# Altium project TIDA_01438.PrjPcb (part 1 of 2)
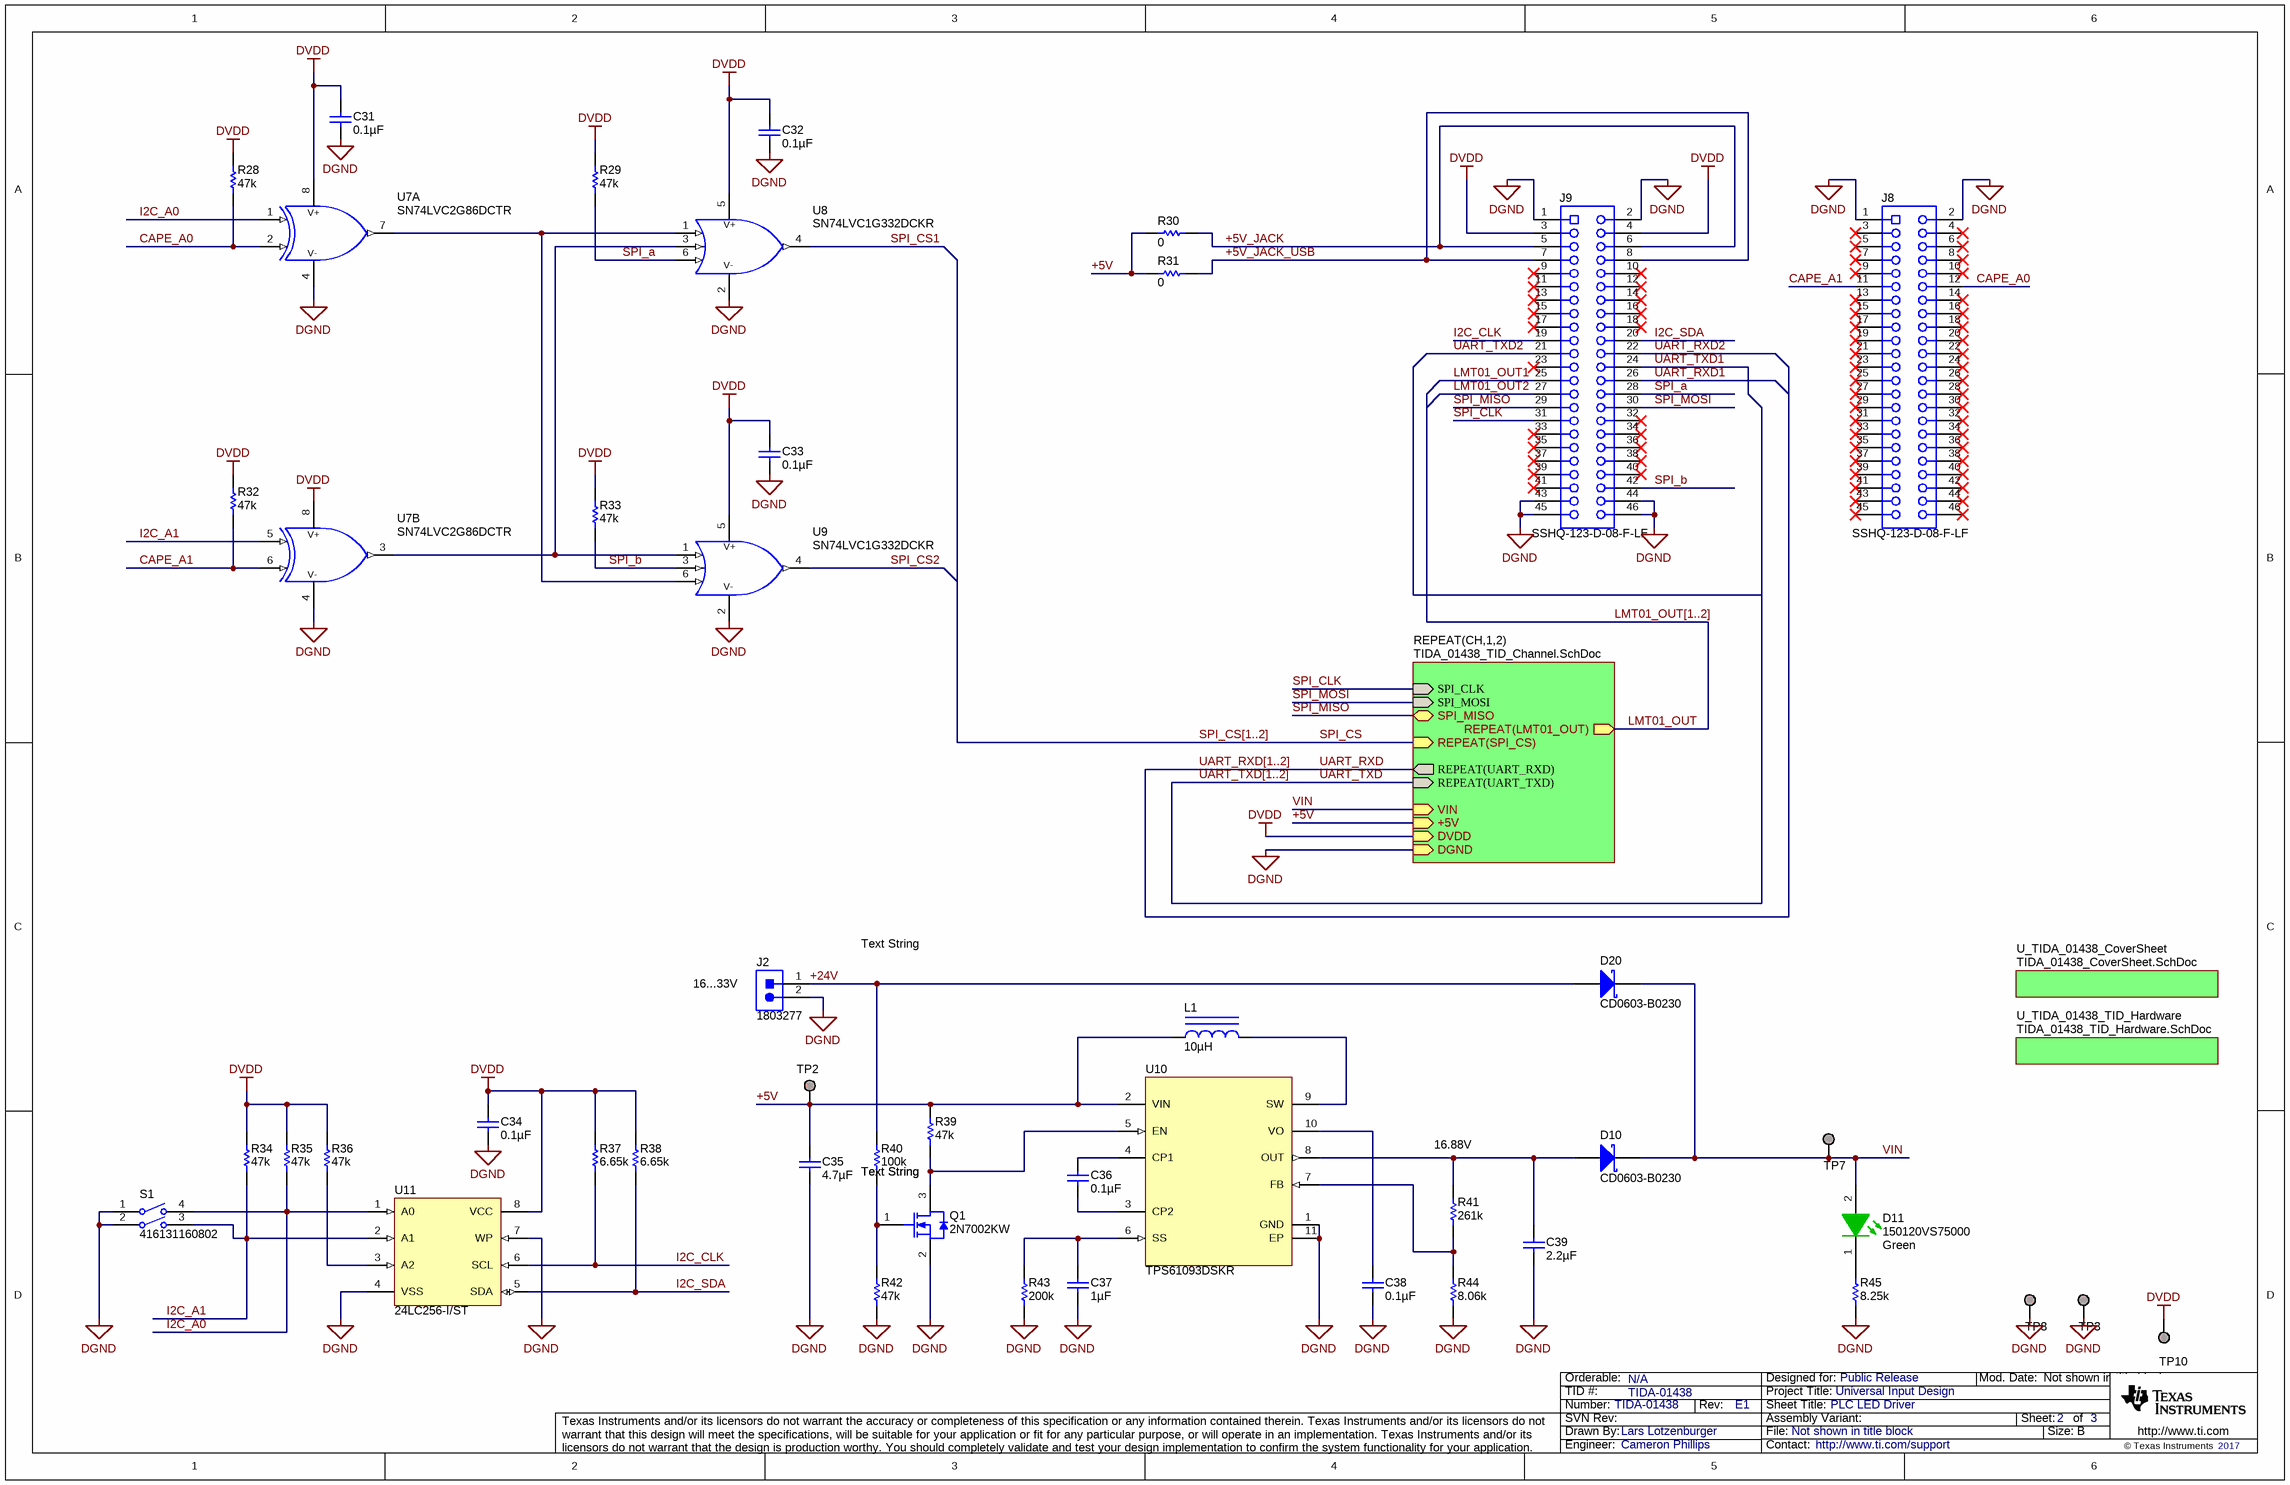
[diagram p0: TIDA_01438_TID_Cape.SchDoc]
TID: TIDA-01438; TechSupport: http://www.ti.com/support; SCH_Rev: E1; PRJ_Title: Universal Input Design; PRJ_Number: TIDA-01438; PRJ_Engineer: Cameron Phillips; PRJ_Customer: Public Release; PCB_Rev: E1; PCB_Layout: Cameron Phillips; EVM_Orderable: N/A; CopyrightYear: 2017
8 sheets, 365 parts. Net scope: strictly hierarchical (ports join the sheet entries above them; power ports are local).
Board file: TIDA_01438_TID.PcbDoc
Sheets:
  TIDA_01438_TID_Cape.SchDoc
    CH1 = TIDA_01438_TID_Channel.SchDoc
      AFE = TIDA_01438_TID_AFE.SchDoc
      PWR = TIDA_01438_TID_Power.SchDoc
      ADC = TIDA_01438_TID_ADS1262.SchDoc
      HART = TIDA_01438_TID_HART.SchDoc
    CH2 = TIDA_01438_TID_Channel.SchDoc
      AFE = TIDA_01438_TID_AFE.SchDoc
      PWR = TIDA_01438_TID_Power.SchDoc
      ADC = TIDA_01438_TID_ADS1262.SchDoc
      HART = TIDA_01438_TID_HART.SchDoc
    U_TIDA_01438_CoverSheet = TIDA_01438_CoverSheet.SchDoc
    U_TIDA_01438_TID_Hardware = TIDA_01438_TID_Hardware.SchDoc

## Sheet TIDA_01438_TID_Cape.SchDoc: PLC LED Driver
size 431 x 279 mm; Date: Not shown in title block; ApprovedBy: Not shown in title block; CheckedBy: Not shown in title block; Author: Not shown in title block; CompanyName: Not shown in title block; DrawnBy: Lars Lotzenburger; Engineer: Not shown in title block; Organization: Not shown in title block; Address1: Not shown in title block; Address2: Not shown in title block; Address3: Not shown in title block; Address4: Not shown in title block; DocumentNumber: 2; Revision: Use project parameter SCH_Rev; SheetNumber: 2; SheetTotal: 3; PageSetup: Record=PageOptions¦CenterHorizontal=True¦CenterVertical=True¦PrintScale=0.62¦XCorrection=1.00¦YCorrection=1.00¦PrintKind=0¦BorderSize=5000000¦LeftOffset=0¦BottomOffset=0¦Orientation=2¦PaperLength=1000¦PaperWidth=1000¦Scale=100¦PaperSource=15¦PrintQuality=600¦MediaType=1¦DitherType=10¦PrintScaleMode=1¦PaperKind=Letter

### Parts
C31  ValueDisplayed: 0.1µF  [0402]  (hidden comment: C1005X7R1H104K)
C32  ValueDisplayed: 0.1µF  [0402]  (hidden comment: C1005X7R1H104K)
C33  ValueDisplayed: 0.1µF  [0402]  (hidden comment: C1005X7R1H104K)
C34  ValueDisplayed: 0.1µF  [0402]  (hidden comment: C1005X7R1H104K)
C35  ValueDisplayed: 4.7µF  [1206_190]  (hidden comment: C3216X7R1H475M160AC)
C36  ValueDisplayed: 0.1µF  [0402]  (hidden comment: C1005X7R1H104K)
C37  ValueDisplayed: 1µF  [0603]  (hidden comment: C1608X7R1C105K)
C38  ValueDisplayed: 0.1µF  [0402]  (hidden comment: C1005X7R1H104K)
C39  ValueDisplayed: 2.2µF  [1206]  (hidden comment: UMK316B7225KL-T)
D10  CD0603-B0230  [Diode_0603]
D11  150120VS75000  value Green  [WL_SMCW_GREEN_1206]
D20  CD0603-B0230  [Diode_0603]
J2  1803277  [PhoenixContact_1803277]
J8  SSHQ-123-D-08-F-LF  [Major_BBB_SSHQ-123-D-08]
J9  SSHQ-123-D-08-F-LF  [Major_BBB_SSHQ-123-D-08]
L1  ValueDisplayed: 10µH  [WE-LQS_4018]  (hidden comment: 74404042100)
Q1  2N7002KW  [SOT-323]
R28  ValueDisplayed: 47k  [0402]  (hidden comment: CRCW040247K0JNED)
R29  ValueDisplayed: 47k  [0402]  (hidden comment: CRCW040247K0JNED)
R30  ValueDisplayed: 0  [0603]  (hidden comment: ERJ-3GEY0R00V)
R31  ValueDisplayed: 0  [0603]  (hidden comment: ERJ-3GEY0R00V)
R32  ValueDisplayed: 47k  [0402]  (hidden comment: CRCW040247K0JNED)
R33  ValueDisplayed: 47k  [0402]  (hidden comment: CRCW040247K0JNED)
R34  ValueDisplayed: 47k  [0402]  (hidden comment: CRCW040247K0JNED)
R35  ValueDisplayed: 47k  [0402]  (hidden comment: CRCW040247K0JNED)
R36  ValueDisplayed: 47k  [0402]  (hidden comment: CRCW040247K0JNED)
R37  ValueDisplayed: 6.65k  [0402]  (hidden comment: CRCW04026K65FKED)
R38  ValueDisplayed: 6.65k  [0402]  (hidden comment: CRCW04026K65FKED)
R39  ValueDisplayed: 47k  [0402]  (hidden comment: CRCW040247K0JNED)
R40  ValueDisplayed: 100k  [0402]  (hidden comment: CRCW0402100KFKED)
R41  ValueDisplayed: 261k  [0402]  (hidden comment: CRCW0402261KFKED)
R42  ValueDisplayed: 47k  [0402]  (hidden comment: CRCW040247K0JNED)
R43  ValueDisplayed: 200k  [0402]  (hidden comment: CRCW0402200KFKED)
R44  ValueDisplayed: 8.06k  [0402]  (hidden comment: CRCW04028K06FKED)
R45  ValueDisplayed: 8.25k  [0402]  (hidden comment: CRCW04028K25FKED)
S1  416131160802  [SW_416131160802]
TP2  TESTPOINT  [TESTPOINT]  (value not drawn)  (no BOM)
TP3  TESTPOINT  [TESTPOINT]  (value not drawn)  (no BOM)
TP7  TESTPOINT  [TESTPOINT]  (value not drawn)  (no BOM)
TP8  TESTPOINT  [TESTPOINT]  (value not drawn)  (no BOM)
TP10  TESTPOINT  [TESTPOINT]  (value not drawn)  (no BOM)
U7  SN74LVC2G86DCTR  [DCT0008A_N]  (parts A,B of 2)
U8  SN74LVC1G332DCKR  [DCK0006A_N]
U9  SN74LVC1G332DCKR  [DCK0006A_N]
U10  TPS61093DSKR  [DSK0010A]
U11  24LC256-I/ST  [TSSOP-8]

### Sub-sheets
REPEAT(CH,1,2) = TIDA_01438_TID_Channel.SchDoc: SPI_CLK (in), SPI_MOSI (in), REPEAT(UART_RXD) (out), REPEAT(UART_TXD) (in), REPEAT(SPI_CS) (in), SPI_MISO, VIN (in), +5V (in), DGND (in), DVDD (in), REPEAT(LMT01_OUT) (out)
U_TIDA_01438_CoverSheet = TIDA_01438_CoverSheet.SchDoc: no entries
U_TIDA_01438_TID_Hardware = TIDA_01438_TID_Hardware.SchDoc: no entries

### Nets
DGND: C31.2 C32.2 C33.2 C34.2 C35.2 C37.2 C38.2 C39.2 J2.2 J8.1 J8.2 J9.1 J9.2 J9.43 J9.44 J9.45 J9.46 Q1.2(S) R42.1 R43.2 R44.1 R45.1 S1.1 S1.2 TP3.1 TP8.1 U7.4(GND) U8.2(GND) U9.2(GND) U10.1(GND) U10.11(EP) U11.4(VSS) U11.7(WP) ; sheet REPEAT(CH,1,2)/DGND
DVDD: C31.1 C32.1 C33.1 C34.1 J9.3 J9.4 R28.1 R29.1 R32.1 R33.1 R34.1 R35.1 R36.1 R37.1 R38.1 TP10.1 U7.8(VCC) U8.5(VCC) U9.5(VCC) U11.8(VCC) ; sheet REPEAT(CH,1,2)/DVDD
+5V: C35.1 L1.1 R30.1 R31.1 R39.2 TP2.1 U10.2(VIN) ; sheet REPEAT(CH,1,2)/+5V
+5V_JACK: J9.5 J9.6 R30.2
+5V_JACK_USB: J9.7 J9.8 R31.2
+24V: D20.2(A) J2.1 R40.2
CAPE_A0: J8.12 R28.2 U7.2(1B)
CAPE_A1: J8.11 R32.2 U7.6(2B)
I2C_A0: R35.2 S1.4 U7.1(1A) U11.1(A0)
I2C_A1: R34.2 S1.3 U7.5(2A) U11.2(A1)
I2C_CLK: J9.19 R37.2 U11.6(SCL)
I2C_SDA: J9.20 R38.2 U11.5(SDA)
LMT01_OUT1: J9.25
LMT01_OUT2: J9.27
SPI_a: J9.28 R29.2 U8.6(C)
SPI_b: J9.42 R33.2 U9.3(B)
SPI_CLK: J9.31 ; sheet REPEAT(CH,1,2)/SPI_CLK
SPI_CS1: U8.4(Y)
SPI_CS2: U9.4(Y)
SPI_MISO: J9.29 ; sheet REPEAT(CH,1,2)/SPI_MISO
SPI_MOSI: J9.30 ; sheet REPEAT(CH,1,2)/SPI_MOSI
UART_RXD1: J9.26
UART_RXD2: J9.22
UART_TXD1: J9.24
UART_TXD2: J9.21
VIN: D10.1(K) D11.2(A) D20.1(K) TP7.1 ; sheet REPEAT(CH,1,2)/VIN
NetC36_1: C36.1 U10.4(CP1)
NetC36_2: C36.2 U10.3(CP2)
NetC37_1: C37.1 R43.1 U10.6(SS)
NetC38_1: C38.1 U10.10(VO)
NetC39_1: C39.1 D10.2(A) R41.2 U10.8(OUT)
NetD11_1: D11.1(K) R45.2
NetL1_2: L1.2 U10.9(SW)
NetQ1_1: Q1.1(G) R40.1 R42.2
NetQ1_3: Q1.3(D) R39.1 U10.5(EN)
NetR36_2: R36.2 U11.3(A2)
NetR41_1: R41.1 R44.2 U10.7(FB)
NetU7_3: U7.3(2Y) U8.3(B) U9.1(A)
NetU7_7: U7.7(1Y) U8.1(A) U9.6(C)

Not connected (* = marked no-connect by the designer): J8 3* 4* 5* 6* 7* 8* 9* 10* 13* 14* 15* 16* 17* 18* 19* 20* 21* 22* 23* 24* 25* 26* 27* 28* 29* 30* 31* 32* 33* 34* 35* 36* 37* 38* 39* 40* 41* 42* 43* 44* 45* 46*; J9 9* 10* 11* 12* 13* 14* 15* 16* 17* 18* 23* 32* 33* 34* 35* 36* 37* 38* 39* 40* 41*

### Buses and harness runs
bus LMT01_OUT[1..2]
bus SPI_CS[1..2]
bus UART_RXD[1..2]
bus UART_TXD[1..2]

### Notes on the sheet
- Text String
- (near J2) 16...33V
- (near R40) Text String
- (near R41) 16.88V

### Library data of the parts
C31-C34 C36 C38 = C1005X7R1H104K: CAP, CERM, 0.1 µF, 50 V, +/- 10%, X7R, 0402; Manufacturer: TDK; Polarized: N; CompType: Capacitor; Value: 0.1uF; U/M: EA; Cap_F: 0.0000001; Tolerance_%: 10; Value1: Unknown; VDC_V: 50; Value2: 50V; TaMin_C: -55; TaMax_C: 125; AEC Category: Q200
C35 = C3216X7R1H475M160AC: CAP, CERM, 4.7 µF, 50 V, +/- 20%, X7R, 1206_190; Manufacturer: TDK; Polarized: N; CompType: Capacitor; Value: 4.7uF; U/M: EA; Cap_F: 0.0000047; Tolerance_%: 20; Value1: Unknown; VDC_V: 50; Value2: 50V; TaMin_C: -55; TaMax_C: 125; Cap_Case: 1206; AEC Category: Q200
C37 = C1608X7R1C105K: CAP, CERM, 1 µF, 16 V, +/- 10%, X7R, 0603; Manufacturer: TDK; Polarized: N; CompType: Capacitor; Value: 1uF; U/M: EA; Cap_F: 0.000001; Tolerance_%: 10; ESR_ohm: 0.0057; Value1: 0.0057 ohm; VDC_V: 16; Value2: 16V; TaMin_C: -55; TaMax_C: 125
C39 = UMK316B7225KL-T: CAP, CERM, 2.2 µF, 50 V, +/- 10%, X7R, 1206; Manufacturer: Taiyo Yuden; Polarized: N; CompType: Capacitor; Value: 2.2uF; U/M: EA; Cap_F: 0.0000022; Tolerance_%: 10; Value1: Unknown; VDC_V: 50; Value2: 50V; TaMin_C: -55; TaMax_C: 125; AEC Category: Q200
D10 D20 = CD0603-B0230: Diode, Schottky, 35 V, 0.2 A, 0603 Diode; Manufacturer: Bourns; U/M: EA; Vf_V: 0.5; Value: 35V; Value1: 0.2A; Value2: 0.5V; Io_A: 0.2; Vr_V: 35; TJmax_C: 125; AEC Category: Q101
D11 = 150120VS75000: LED, Green, SMD; Manufacturer: Wurth Elektronik; SymbolCreator: Altium; Type: AlInGaP; Vf_V: 2; Value2: 2V; Io_A: 0.02; Vr_V: 5; Ir_A: 1e-005; Tjmax_C: 85; Power_TotalModule: 0.072; Value1: 0.072W; Angle: 140; U/M: EA
J2 = 1803277: Terminal Block, 2x1, 3.81mm, R/A, TH; Manufacturer: Phoenix Contact; SymbolCreator: a0412235; U/M: EA
J8 J9 = SSHQ-123-D-08-F-LF: Female Connector, 2.54mm, 23x2, TH; Manufacturer: Major League Electronics; SymbolCreator: Altium; CompType: Receptacle; U/M: EA
L1 = 74404042100: Inductor, Wirewound, Ferrite, 10 µH, 1.2 A, 0.15 ohm, SMD; Manufacturer: Wurth Elektronik; Value: 10uH; Ind_H: 10.0E-6; Imax_A: 1.2; Irms: 1.2A @ 40C rise; Isat: 1.5A @ 30% inductance drop; DCR_ohm: 0.15; Value2: 1.2A; AEC Category: Q200; AEC Qualified: N
Q1 = 2N7002KW: MOSFET, N-CH, 60 V, 0.31 A, SOT-323; Manufacturer: Fairchild Semiconductor; Alternate Manufacturer: None; U/M: EA; ChType: N; Value: 60V; VdsMax_V: 60; Value1: 1.6 ohm; Rdson45_ohm: 1.6; Value2: ? nC; Vgs_V: 2.1; IdsMax_A: 0.31; AEC Category: Q101
R28 R29 R32 R33 = CRCW040247K0JNED: RES, 47 k, 5%, 0.063 W, 0402; Manufacturer: Vishay-Dale; CompType: Resistor; Value: 47k; Res_ohm: 47000; Value_Code: 47k0; Tolerance_%: 5; Power_W: 0.063; Value2: 0.063W; VDC_V: 50; TempCo: 200 ppm/C; EIA_Code: E24; U/M: EA
R30 R31 = ERJ-3GEY0R00V: RES, 0, 5%, 0.1 W, 0603; Manufacturer: Panasonic; CompType: Resistor; Value: 0; Value_Code: 0000; Tolerance_%: 5; Power_W: 0.1; Value2: 0.1W; VDC_V: 50; TempCo: 600 ppm/C; EIA_Code: E24; U/M: EA; AEC Category: Q200
R34-R36 R39 R42 = CRCW040247K0JNED: RES, 47 k, 5%, 0.063 W, 0402; Manufacturer: Vishay-Dale; CompType: Resistor; Value: 47k; Res_ohm: 47000; Value_Code: 47k0; Tolerance_%: 5; Power_W: 0.063; Value2: 0.063W; VDC_V: 50; TempCo: 200 ppm/C; EIA_Code: E24; U/M: EA; AEC Category: Q200
R37 R38 = CRCW04026K65FKED: RES, 6.65 k, 1%, 0.063 W, 0402; Manufacturer: Vishay-Dale; CompType: Resistor; Value: 6.65k; Res_ohm: 6650; Value_Code: 6k65; Tolerance_%: 1; Power_W: 0.063; Value2: 0.063W; VDC_V: 50; TempCo: 100 ppm/C; EIA_Code: E96; U/M: EA; AEC Category: Q200
R40 = CRCW0402100KFKED: RES, 100 k, 1%, 0.063 W, 0402; Manufacturer: Vishay-Dale; CompType: Resistor; Value: 100k; Res_ohm: 100000; Tolerance_%: 1; Power_W: 0.063; Value2: 0.063W; VDC_V: 50; TempCo: 100 ppm/C; EIA_Code: E96; U/M: EA; AEC Category: Q200
R41 = CRCW0402261KFKED: RES, 261 k, 1%, 0.063 W, 0402; Manufacturer: Vishay-Dale; CompType: Resistor; Value: 261k; Res_ohm: 261000; Tolerance_%: 1; Power_W: 0.063; Value2: 0.063W; VDC_V: 50; TempCo: 100 ppm/C; EIA_Code: E96; U/M: EA; AEC Category: Q200
R43 = CRCW0402200KFKED: RES, 200 k, 1%, 0.063 W, 0402; Manufacturer: Vishay-Dale; CompType: Resistor; Value: 200k; Res_ohm: 200000; Tolerance_%: 1; Power_W: 0.063; Value2: 0.063W; VDC_V: 50; TempCo: 100 ppm/C; EIA_Code: E96; U/M: EA; AEC Category: Q200
R44 = CRCW04028K06FKED: RES, 8.06 k, 1%, 0.063 W, 0402; Manufacturer: Vishay-Dale; CompType: Resistor; Value: 8.06k; Res_ohm: 8060; Value_Code: 8k06; Tolerance_%: 1; Power_W: 0.063; Value2: 0.063W; VDC_V: 50; TempCo: 100 ppm/C; EIA_Code: E96; U/M: EA; AEC Category: Q200
R45 = CRCW04028K25FKED: RES, 8.25 k, 1%, 0.063 W, 0402; Manufacturer: Vishay-Dale; CompType: Resistor; Value: 8.25k; Res_ohm: 8250; Value_Code: 8k25; Tolerance_%: 1; Power_W: 0.063; Value2: 0.063W; VDC_V: 50; TempCo: 100 ppm/C; EIA_Code: E96; U/M: EA; AEC Category: Q200
S1 = 416131160802: Switch, SPST, Off-On, 2 Pos, SMD; Manufacturer: Wurth Elektronik; SymbolCreator: Altium; VDC_V: 24; PositionCount: 2; CurrentRating_mA: 25
TP2 TP3 TP7 TP8 TP10 = TESTPOINT: TEST POINT.  No entry in BOM.
U7 = SN74LVC2G86DCTR: Dual 2-Input Exclusive-OR Gate, DCT0008A; Manufacturer: Texas Instruments; SymbolCreator: a0411947; CompType: IC; U/M: EA
U8 U9 = SN74LVC1G332DCKR: Single 3-Input Positive-OR Gate, DCK0006A; Manufacturer: Texas Instruments; SymbolCreator: Altium; CompType: IC; U/M: EA
U10 = TPS61093DSKR: LOW INPUT BOOST CONVERTER WITH INTEGRATED POWER DIODE AND INPUT/OUTPUT ISOLATION, DSK0010A; Manufacturer: Texas Instruments; SymbolCreator: Altium; CompType: IC; U/M: EA
U11 = 24LC256-I/ST: 256K I2C CMOS Serial EEPROM, TSSOP-8; Manufacturer: Microchip; SymbolCreator: a0411947

## Sheet TIDA_01438_TID_Channel.SchDoc
size 431 x 279 mm; Date: Not shown in title block; ApprovedBy: Not shown in title block; CheckedBy: Not shown in title block; Author: Not shown in title block; CompanyName: Not shown in title block; Engineer: Not shown in title block; Organization: Not shown in title block; Address1: Not shown in title block; Address2: Not shown in title block; Address3: Not shown in title block; Address4: Not shown in title block; DocumentNumber: 1; Revision: Use project parameter SCH_Rev; SheetNumber: 2; SheetTotal: 3; PageSetup: Record=PageOptions¦CenterHorizontal=True¦CenterVertical=True¦PrintScale=1.00¦XCorrection=1.00¦YCorrection=1.00¦PrintKind=0¦BorderSize=5000000¦LeftOffset=0¦BottomOffset=0¦Orientation=2¦PaperLength=1000¦PaperWidth=1000¦Scale=100¦PaperSource=15¦PrintQuality=600¦MediaType=1¦DitherType=10¦PaperKind=Letter¦PrintScaleMode=1
Used 2 times, as channels CH1, CH2. Parts and nets are listed once, with the designators drawn on the sheet.
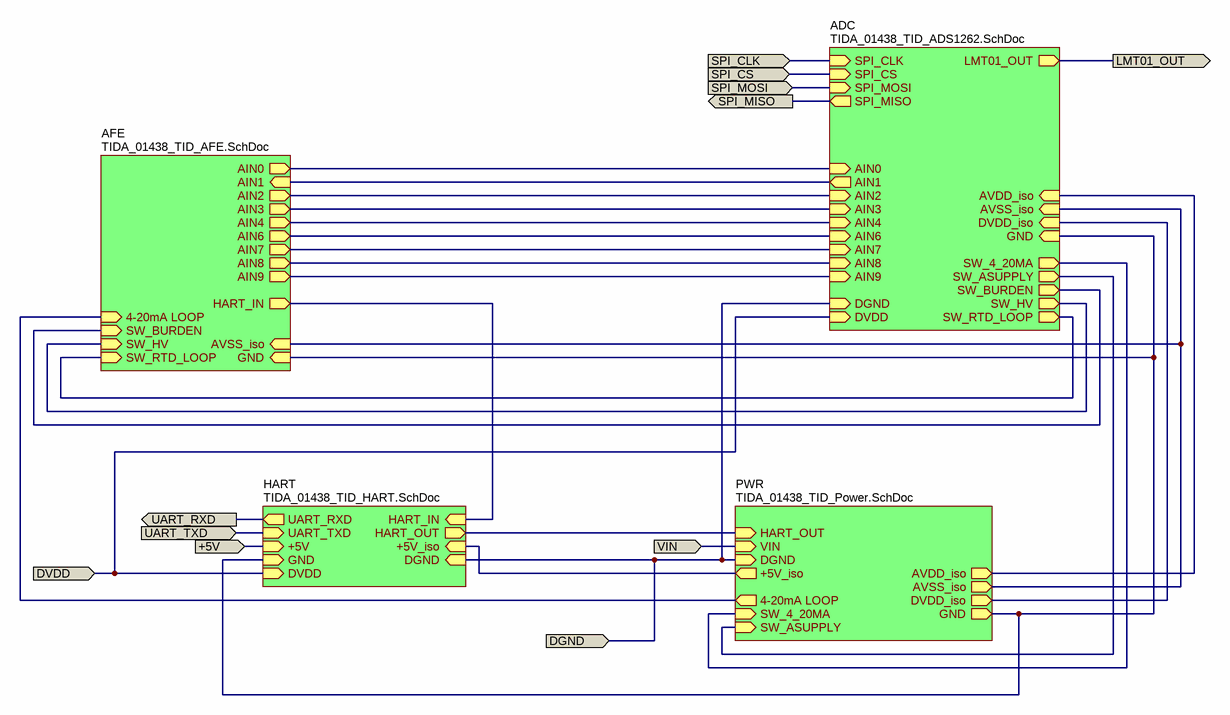
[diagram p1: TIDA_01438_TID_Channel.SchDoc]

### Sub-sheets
ADC = TIDA_01438_TID_ADS1262.SchDoc: SPI_CLK (in), SPI_MOSI (in), SPI_CS (in), AIN8 (in), AIN9 (in), AIN0 (in), AIN7 (in), AIN6 (in), AIN4 (in), SW_RTD_LOOP (out), SW_HV (out), SW_BURDEN (out), SW_4_20MA (out), SW_ASUPPLY (out), AIN1 (out), AIN2 (in), AIN3 (in), SPI_MISO (out), GND (in), AVSS_iso (in), DVDD_iso (in), AVDD_iso (in), DGND (in), DVDD (in), LMT01_OUT (out)
AFE = TIDA_01438_TID_AFE.SchDoc: AIN0 (out), AIN8 (out), AIN4 (out), AIN6 (out), AIN7 (out), AIN9 (out), HART_IN (out), 4-20mA LOOP (in), SW_RTD_LOOP (in), SW_HV (in), SW_BURDEN (in), AIN1 (in), AIN2 (out), AIN3 (out), GND (in), AVSS_iso (in)
HART = TIDA_01438_TID_HART.SchDoc: HART_IN (in), UART_RXD (out), UART_TXD (in), HART_OUT (out), GND (in), +5V (in), DGND (in), DVDD (in), +5V_iso (in)
PWR = TIDA_01438_TID_Power.SchDoc: HART_OUT (in), 4-20mA LOOP (out), SW_4_20MA (in), VIN (in), GND (out), AVSS_iso (out), DVDD_iso (out), AVDD_iso (out), SW_ASUPPLY (in), DGND (in), +5V_iso (out)

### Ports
+5V (in), DGND (in), DVDD (in), LMT01_OUT (out), SPI_CLK (in), SPI_CS (in), SPI_MISO, SPI_MOSI (in), UART_RXD (out), UART_TXD (in), VIN (in)

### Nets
+5V: port +5V, sheet HART/+5V
DGND: port DGND, sheet PWR/DGND, sheet ADC/DGND, sheet HART/DGND
DVDD: port DVDD, sheet ADC/DVDD, sheet HART/DVDD
LMT01_OUT: port LMT01_OUT, sheet ADC/LMT01_OUT
SPI_CLK: port SPI_CLK, sheet ADC/SPI_CLK
SPI_CS: port SPI_CS, sheet ADC/SPI_CS
SPI_MISO: port SPI_MISO, sheet ADC/SPI_MISO
SPI_MOSI: port SPI_MOSI, sheet ADC/SPI_MOSI
UART_RXD: port UART_RXD, sheet HART/UART_RXD
UART_TXD: port UART_TXD, sheet HART/UART_TXD
VIN: port VIN, sheet PWR/VIN
(unnamed): sheet AFE/AIN0, sheet ADC/AIN0
(unnamed): sheet AFE/AIN8, sheet ADC/AIN8  [a separate net that carries the same name]
(unnamed): sheet AFE/AIN4, sheet ADC/AIN4  [a separate net that carries the same name]
(unnamed): sheet AFE/AIN6, sheet ADC/AIN6  [a separate net that carries the same name]
(unnamed): sheet AFE/AIN7, sheet ADC/AIN7  [a separate net that carries the same name]
(unnamed): sheet AFE/AIN9, sheet ADC/AIN9  [a separate net that carries the same name]
(unnamed): sheet AFE/HART_IN, sheet HART/HART_IN  [a separate net that carries the same name]
(unnamed): sheet AFE/4-20mA LOOP, sheet PWR/4-20mA LOOP  [a separate net that carries the same name]
(unnamed): sheet AFE/SW_RTD_LOOP, sheet ADC/SW_RTD_LOOP  [a separate net that carries the same name]
(unnamed): sheet AFE/SW_HV, sheet ADC/SW_HV  [a separate net that carries the same name]
(unnamed): sheet AFE/SW_BURDEN, sheet ADC/SW_BURDEN  [a separate net that carries the same name]
(unnamed): sheet AFE/AIN1, sheet ADC/AIN1  [a separate net that carries the same name]
(unnamed): sheet AFE/AIN2, sheet ADC/AIN2  [a separate net that carries the same name]
(unnamed): sheet AFE/AIN3, sheet ADC/AIN3  [a separate net that carries the same name]
(unnamed): sheet AFE/GND, sheet PWR/GND, sheet ADC/GND, sheet HART/GND  [a separate net that carries the same name]
(unnamed): sheet AFE/AVSS_iso, sheet PWR/AVSS_iso, sheet ADC/AVSS_iso  [a separate net that carries the same name]
(unnamed): sheet PWR/HART_OUT, sheet HART/HART_OUT  [a separate net that carries the same name]
(unnamed): sheet PWR/SW_4_20MA, sheet ADC/SW_4_20MA  [a separate net that carries the same name]
(unnamed): sheet PWR/DVDD_iso, sheet ADC/DVDD_iso  [a separate net that carries the same name]
(unnamed): sheet PWR/AVDD_iso, sheet ADC/AVDD_iso  [a separate net that carries the same name]
(unnamed): sheet PWR/SW_ASUPPLY, sheet ADC/SW_ASUPPLY  [a separate net that carries the same name]
(unnamed): sheet PWR/+5V_iso, sheet HART/+5V_iso  [a separate net that carries the same name]

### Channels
CH1: ports +5V=+5V DGND=DGND DVDD=DVDD LMT01_OUT=LMT01_OUT1 SPI_CLK=SPI_CLK SPI_CS=SPI_CS1 SPI_MISO=SPI_MISO SPI_MOSI=SPI_MOSI UART_RXD=UART_RXD1 UART_TXD=UART_TXD1 VIN=VIN
CH2: ports +5V=+5V DGND=DGND DVDD=DVDD LMT01_OUT=LMT01_OUT2 SPI_CLK=SPI_CLK SPI_CS=SPI_CS2 SPI_MISO=SPI_MISO SPI_MOSI=SPI_MOSI UART_RXD=UART_RXD2 UART_TXD=UART_TXD2 VIN=VIN

## Sheet TIDA_01438_TID_AFE.SchDoc
size 431 x 279 mm; Date: Not shown in title block; ApprovedBy: Not shown in title block; CheckedBy: Not shown in title block; Author: Not shown in title block; CompanyName: Not shown in title block; Engineer: Not shown in title block; Organization: Not shown in title block; Address1: Not shown in title block; Address2: Not shown in title block; Address3: Not shown in title block; Address4: Not shown in title block; DocumentNumber: 1; Revision: Use project parameter SCH_Rev; SheetNumber: 2; SheetTotal: 3; PageSetup: Record=PageOptions¦CenterHorizontal=True¦CenterVertical=True¦PrintScale=0.66¦XCorrection=1.00¦YCorrection=1.00¦PrintKind=0¦BorderSize=5000000¦LeftOffset=0¦BottomOffset=0¦Orientation=2¦PaperLength=2970¦PaperWidth=2100¦Scale=100¦PaperSource=7¦PrintQuality=600¦MediaType=1¦DitherType=10¦PrintScaleMode=1¦PaperKind=A4¦PaperIndex=9
Used 2 times, as channels CH1/AFE, CH2/AFE. Parts and nets are listed once, with the designators drawn on the sheet.
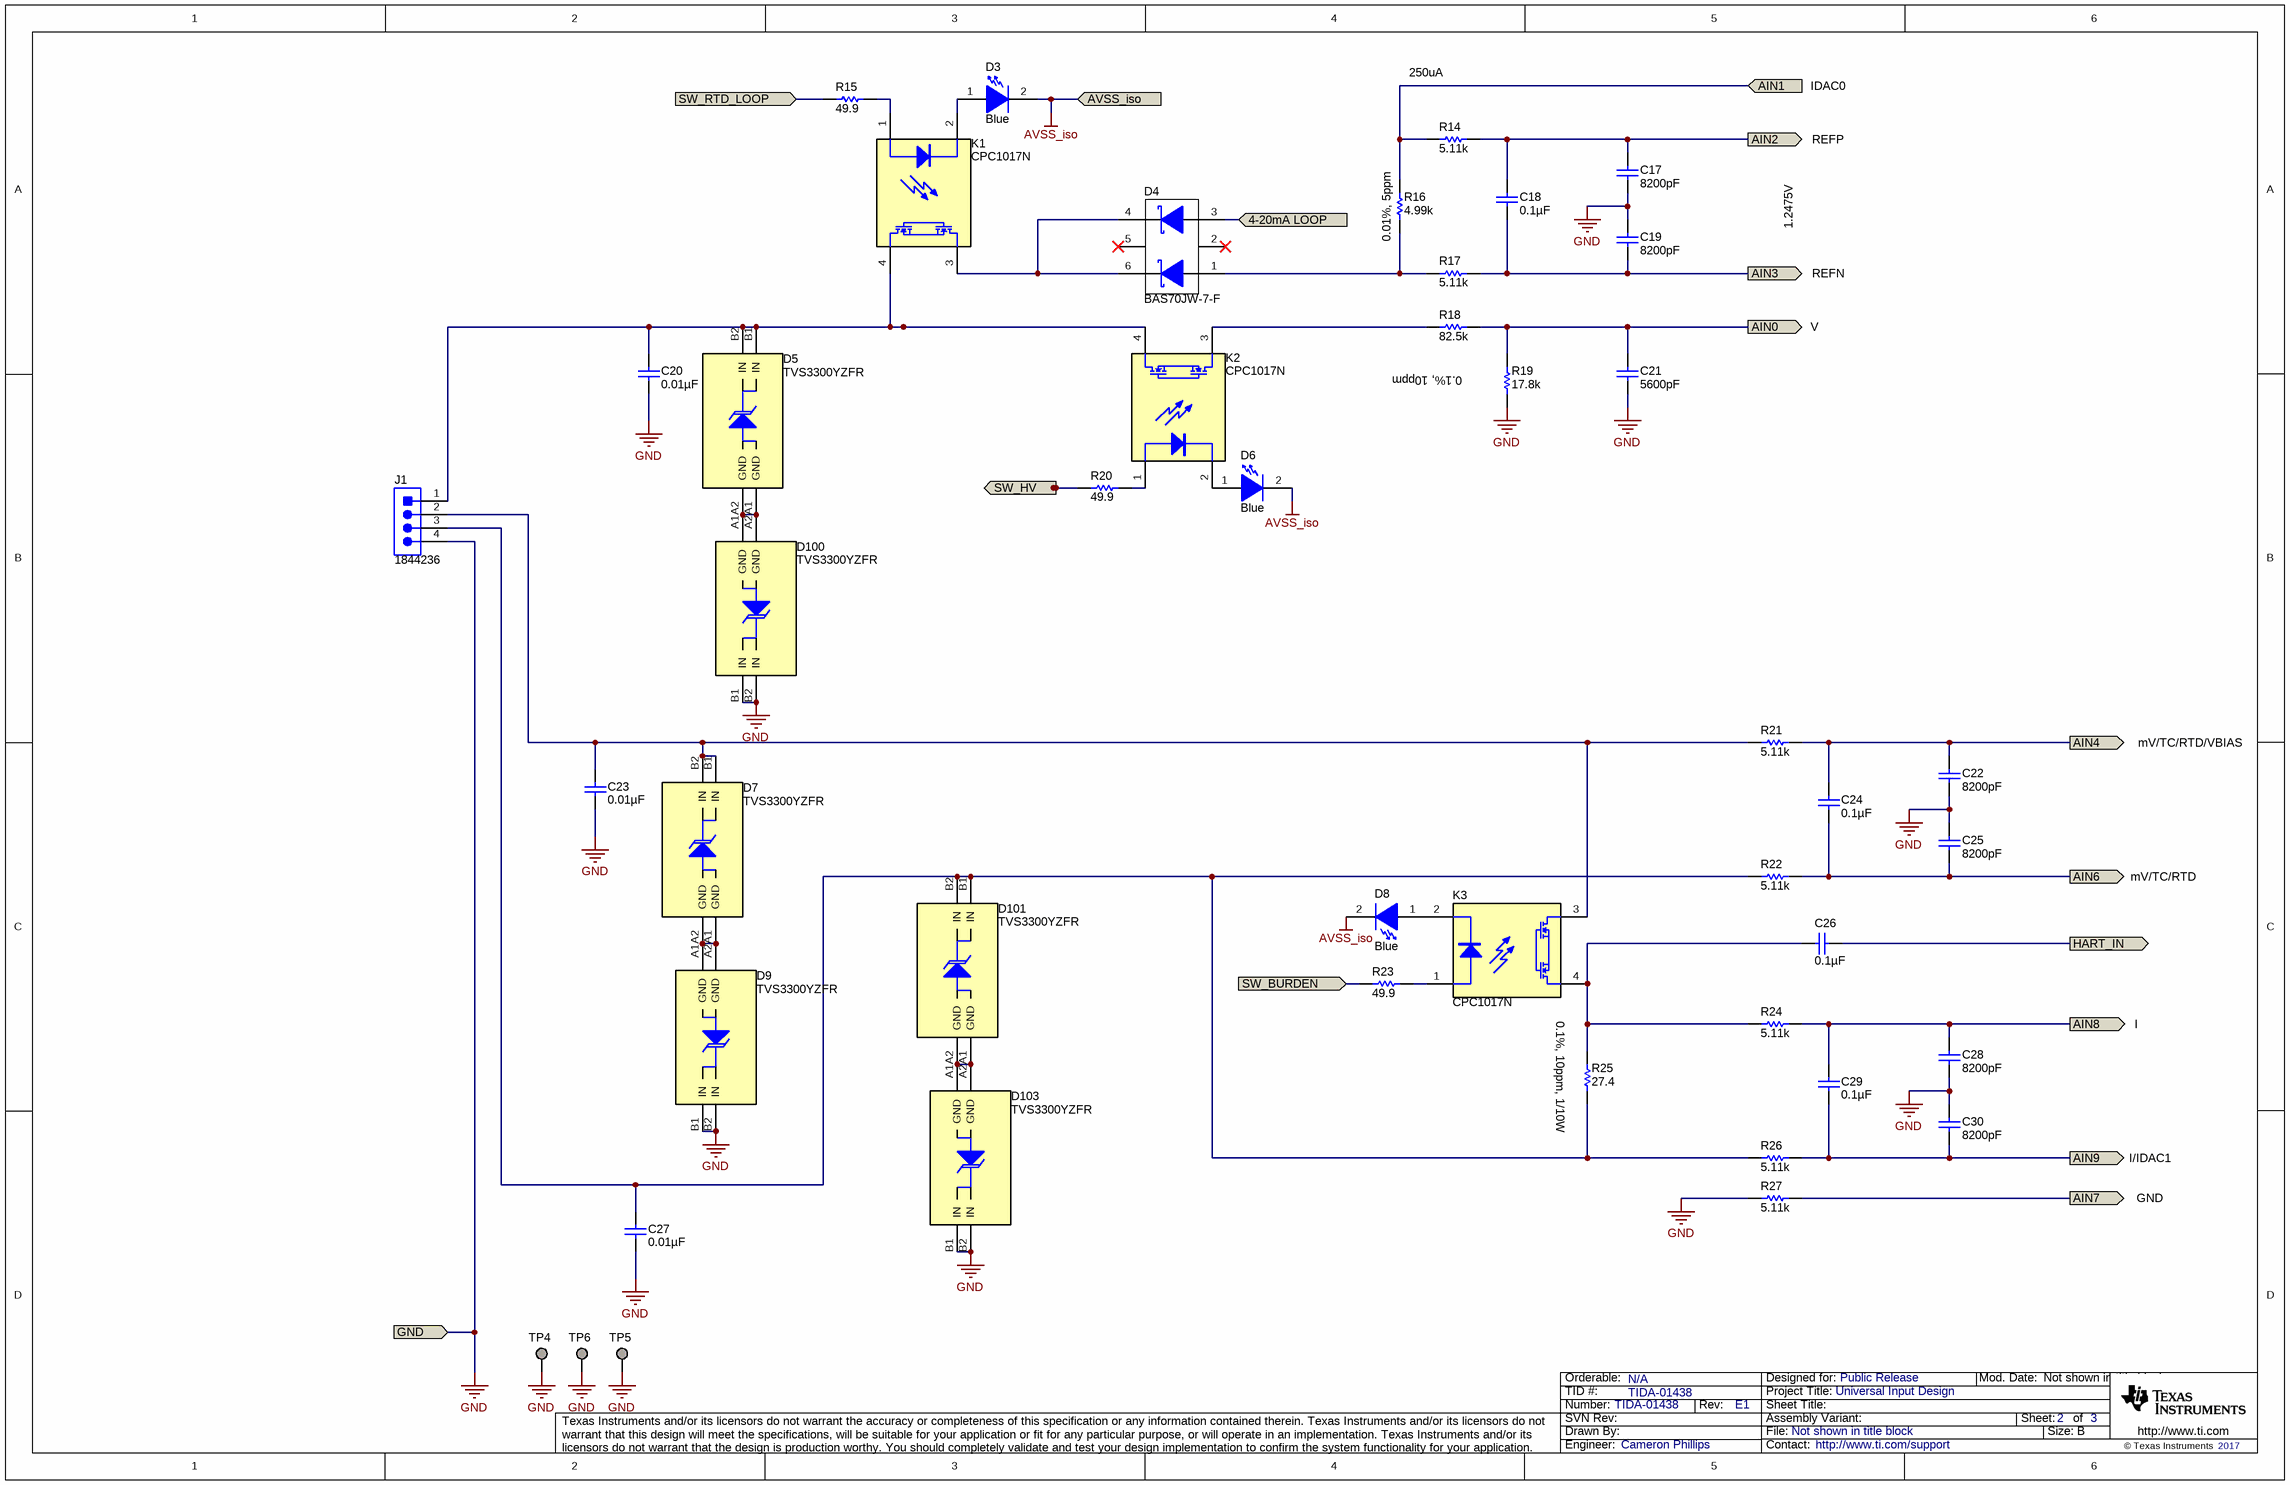
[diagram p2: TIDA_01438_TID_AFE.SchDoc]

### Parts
C17  ValueDisplayed: 8200pF  [0805_HV]  (hidden comment: GRM2195C1H822JA01D)
C18  ValueDisplayed: 0.1µF  [1206_190]  (hidden comment: C3216NP01H104J160AA)
C19  ValueDisplayed: 8200pF  [0805_HV]  (hidden comment: GRM2195C1H822JA01D)
C20  ValueDisplayed: 0.01µF  [0805_HV]  (hidden comment: 08051C103KAT2A)
C21  ValueDisplayed: 5600pF  [0805_HV]  (hidden comment: GRM2195C1H562JA01D)
C22  ValueDisplayed: 8200pF  [0805_HV]  (hidden comment: GRM2195C1H822JA01D)
C23  ValueDisplayed: 0.01µF  [0805_HV]  (hidden comment: 08051C103KAT2A)
C24  ValueDisplayed: 0.1µF  [1206_190]  (hidden comment: C3216NP01H104J160AA)
C25  ValueDisplayed: 8200pF  [0805_HV]  (hidden comment: GRM2195C1H822JA01D)
C26  ValueDisplayed: 0.1µF  [0402]  (hidden comment: C1005X7R1H104K)
C27  ValueDisplayed: 0.01µF  [0805_HV]  (hidden comment: 08051C103KAT2A)
C28  ValueDisplayed: 8200pF  [0805_HV]  (hidden comment: GRM2195C1H822JA01D)
C29  ValueDisplayed: 0.1µF  [1206_190]  (hidden comment: C3216NP01H104J160AA)
C30  ValueDisplayed: 8200pF  [0805_HV]  (hidden comment: GRM2195C1H822JA01D)
D3  value Blue  [LB Q39G_BLUE]  (hidden comment: LB Q39G-L2N2-35-1)
D4  BAS70JW-7-F  [SOT-363]
D5  TVS3300YZFR  [YZF0004-C01]
D6  value Blue  [LB Q39G_BLUE]  (hidden comment: LB Q39G-L2N2-35-1)
D7  TVS3300YZFR  [YZF0004-C01]
D8  value Blue  [LB Q39G_BLUE]  (hidden comment: LB Q39G-L2N2-35-1)
D9  TVS3300YZFR  [YZF0004-C01]
D100  TVS3300YZFR  [YZF0004-C01]
D101  TVS3300YZFR  [YZF0004-C01]
D103  TVS3300YZFR  [YZF0004-C01]
J1  1844236  [Phoenix_1844236]
K1  CPC1017N  [RELAY_CPC1017N]
K2  CPC1017N  [RELAY_CPC1017N]
K3  CPC1017N  [RELAY_CPC1017N]
R14  ValueDisplayed: 5.11k  [0402]  (hidden comment: CRCW04025K11FKED)
R15  ValueDisplayed: 49.9  [0402]  (hidden comment: CRCW040249R9FKED)
R16  ValueDisplayed: 4.99k  [0603]  (hidden comment: RNCF0603TKY4K99)
R17  ValueDisplayed: 5.11k  [0402]  (hidden comment: CRCW04025K11FKED)
R18  ValueDisplayed: 82.5k  [RN73_2A]  (hidden comment: RN73C2A82K5BTDF)
R19  ValueDisplayed: 17.8k  [RN73_2A]  (hidden comment: RN73C2A17K8BTDF)
R20  ValueDisplayed: 49.9  [0402]  (hidden comment: CRCW040249R9FKED)
R21  ValueDisplayed: 5.11k  [0402]  (hidden comment: CRCW04025K11FKED)
R22  ValueDisplayed: 5.11k  [0402]  (hidden comment: CRCW04025K11FKED)
R23  ValueDisplayed: 49.9  [0402]  (hidden comment: CRCW040249R9FKED)
R24  ValueDisplayed: 5.11k  [0402]  (hidden comment: CRCW04025K11FKED)
R25  ValueDisplayed: 27.4  [RN73_2A]  (hidden comment: RN73C2A27R4BTDF)
R26  ValueDisplayed: 5.11k  [0402]  (hidden comment: CRCW04025K11FKED)
R27  ValueDisplayed: 5.11k  [0402]  (hidden comment: CRCW04025K11FKED)
TP4  TESTPOINT  [TESTPOINT]  (value not drawn)  (no BOM)
TP5  TESTPOINT  [TESTPOINT]  (value not drawn)  (no BOM)
TP6  TESTPOINT  [TESTPOINT]  (value not drawn)  (no BOM)

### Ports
4-20mA LOOP (in), AIN0 (out), AIN1 (in), AIN2 (out), AIN3 (out), AIN4 (out), AIN6 (out), AIN7 (out), AIN8 (out), AIN9 (out), AVSS_iso (in), GND (in), HART_IN (out), SW_BURDEN (in), SW_HV (in), SW_RTD_LOOP (in)

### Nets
AVSS_iso: D3.2(K) D6.2(K) D8.2(K) ; port AVSS_iso
GND: C17.2 C19.1 C20.2 C21.2 C22.2 C23.2 C25.1 C27.2 C28.2 C30.1 D9.B1(IN) D9.B2(IN) D100.B1(IN) D100.B2(IN) D103.B1(IN) D103.B2(IN) J1.4 R19.1 R27.1 TP4.1 TP5.1 TP6.1 ; port GND
4-20mA LOOP: D4.3(A) ; port 4-20mA LOOP
AIN0: C21.1 R18.2 R19.2 ; port AIN0
AIN1: R14.1 R16.2 ; port AIN1
AIN2: C17.1 C18.1 R14.2 ; port AIN2
AIN3: C18.2 C19.2 R17.2 ; port AIN3
AIN4: C22.1 C24.1 R21.2 ; port AIN4
AIN6: C24.2 C25.2 R22.2 ; port AIN6
AIN7: R27.2 ; port AIN7
AIN8: C28.1 C29.1 R24.2 ; port AIN8
AIN9: C29.2 C30.2 R26.2 ; port AIN9
HART_IN: C26.2 ; port HART_IN
SW_BURDEN: R23.1 ; port SW_BURDEN
SW_HV: R20.1 ; port SW_HV
SW_RTD_LOOP: R15.1 ; port SW_RTD_LOOP
NetC20_1: C20.1 D5.B1(IN) D5.B2(IN) J1.1 K1.4(LOAD) K2.4(LOAD)
NetC23_1: C23.1 D7.B1(IN) D7.B2(IN) J1.2 K3.3(LOAD) R21.1
NetC26_1: C26.1 K3.4(LOAD) R24.1 R25.2
NetC27_1: C27.1 D101.B1(IN) D101.B2(IN) J1.3 R22.1 R25.1 R26.1
NetD3_1: D3.1(A) K1.2(CONTROL)
NetD4_1: D4.1(A) R16.1 R17.1
NetD4_4: D4.4(C) D4.6(C) K1.3(LOAD)
NetD5_A1: D5.A1(GND) D5.A2(GND) D100.A1(GND) D100.A2(GND)
NetD6_1: D6.1(A) K2.2(CONTROL)
NetD7_A1: D7.A1(GND) D7.A2(GND) D9.A1(GND) D9.A2(GND)
NetD8_1: D8.1(A) K3.2(CONTROL)
NetD101_A1: D101.A1(GND) D101.A2(GND) D103.A1(GND) D103.A2(GND)
NetK1_1: K1.1(CONTROL+) R15.2
NetK2_1: K2.1(CONTROL+) R20.2
NetK2_3: K2.3(LOAD) R18.1
NetK3_1: K3.1(CONTROL+) R23.2

Not connected (* = marked no-connect by the designer): D4 2(NC)* 5(NC)*

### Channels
CH1/AFE: designators end in _AFE1; ports 4-20mA LOOP=4-20mA LOOP AIN0=AIN0 AIN1=AIN1 AIN2=AIN2 AIN3=AIN3 AIN4=AIN4 AIN6=AIN6 AIN7=AIN7 AIN8=AIN8 AIN9=AIN9 AVSS_iso=AVSS_iso GND=GND HART_IN=HART_IN SW_BURDEN=SW_BURDEN SW_HV=SW_HV SW_RTD_LOOP=SW_RTD_LOOP
CH2/AFE: designators end in _AFE2; ports 4-20mA LOOP=4-20mA LOOP AIN0=AIN0 AIN1=AIN1 AIN2=AIN2 AIN3=AIN3 AIN4=AIN4 AIN6=AIN6 AIN7=AIN7 AIN8=AIN8 AIN9=AIN9 AVSS_iso=AVSS_iso GND=GND HART_IN=HART_IN SW_BURDEN=SW_BURDEN SW_HV=SW_HV SW_RTD_LOOP=SW_RTD_LOOP

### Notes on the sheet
- 250uA
- IDAC0
- REFP
- (near R16) 0.01%, 5ppm
- 1.2475V
- REFN
- V
- 0.1%, 10ppm
- mV/TC/RTD/VBIAS
- mV/TC/RTD
- I
- (near R25) 0.1%, 10ppm, 1/10W
- I/IDAC1
- GND

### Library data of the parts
C17 C19 C22 C25 C28 C30 = GRM2195C1H822JA01D: CAP, CERM, 8200 pF, 50 V, +/- 5%, C0G/NP0, 0805; Manufacturer: MuRata; Polarized: N; CompType: Capacitor; Value: 8200pF; U/M: EA; Cap_F: 0.0000000082; Tolerance_%: 5; Value1: Unknown; VDC_V: 50; Value2: 50V; TaMin_C: -55; TaMax_C: 125; Cap_Case: 0805; AEC Category: Q200
C18 C24 C29 = C3216NP01H104J160AA: CAP, CERM, 0.1 µF, 50 V, +/- 5%, C0G/NP0, 1206_190; Manufacturer: TDK; Polarized: N; CompType: Capacitor; Value: 0.1uF; U/M: EA; Cap_F: 0.0000001; Tolerance_%: 5; Value1: Unknown; VDC_V: 50; Value2: 50V; TaMin_C: -55; TaMax_C: 150; Cap_Case: 1206; AEC Category: Q200
C20 C23 C27 = 08051C103KAT2A: CAP, CERM, 0.01 µF, 100 V, +/- 10%, X7R, 0805; Manufacturer: AVX; Polarized: N; CompType: Capacitor; Value: 0.01uF; U/M: EA; Cap_F: 0.00000001; Tolerance_%: 10; ESR_ohm: 0.078; Value1: 0.078 ohm; VDC_V: 100; Value2: 100V; TaMin_C: -55; TaMax_C: 125; Cap_Case: 0805
C21 = GRM2195C1H562JA01D: CAP, CERM, 5600 pF, 50 V, +/- 5%, C0G/NP0, 0805; Manufacturer: MuRata; Polarized: N; CompType: Capacitor; Value: 5600pF; U/M: EA; Cap_F: 0.0000000056; Tolerance_%: 5; Value1: Unknown; VDC_V: 50; Value2: 50V; TaMin_C: -55; TaMax_C: 125; Cap_Case: 0805; AEC Category: Q200
C26 = C1005X7R1H104K: as C31 on sheet TIDA_01438_TID_Cape
D3 D6 D8 = LB Q39G-L2N2-35-1: LED, Blue, SMD; Manufacturer: OSRAM; Vf_V: 2.85; Value2: 2.85V; Io_A: 0.15; Tjmax_C: 95; Value1: W; U/M: EA
D4 = BAS70JW-7-F: Diode, Schottky, 70 V, 0.07 A, SOT-363; Manufacturer: Diodes Inc.; SymbolCreator: a0412235; U/M: EA; Vf_V: 1.7; Value: 70V; Value1: 0.07A; Value2: 1.7V; Io_A: 0.07; Vr_V: 70; AEC Category: Q101
D5 D7 D9 D100 D101 D103 = TVS3300YZFR: 33V Precision Surge Protection Clamp, YZF0004-C01 (DSBGA-4); Alternate PartNumber: TVS3300YZFT; Manufacturer: Texas Instruments; SymbolCreator: Altium; SizeArea_mm2: 1.1984; SizeAreaWB_mm2: 4.3884; SizeX_mm: 1.12; SizeY_mm: 1.07; SizeZ_mm: 0.625; CompType: IC; U/M: EA; Green_Lifecycle: Active; Green_REACh: Passed
J1 = 1844236: Terminal Block, 4x1, 3.5mm, Green, R/A, TH; Manufacturer: Phoenix Contact; SymbolCreator: a0412235; CompType: Header; U/M: EA
K1-K3 = CPC1017N: Relay, SPST-NO (1 Form A), 0.1 A, 1.2 VDC, SMD; Manufacturer: IXYS; SymbolCreator: Altium; Coil Voltage: 1.2 VDC; Contact Rating: 0.1 A; Time Operate (s): 0.01
R14 R17 R21 R22 R24 R26 R27 = CRCW04025K11FKED: RES, 5.11 k, 1%, 0.063 W, 0402; Manufacturer: Vishay-Dale; CompType: Resistor; Value: 5.11k; Res_ohm: 5110; Value_Code: 5k11; Tolerance_%: 1; Power_W: 0.063; Value2: 0.063W; VDC_V: 50; TempCo: 100 ppm/C; EIA_Code: E96; U/M: EA; AEC Category: Q200
R15 R20 R23 = CRCW040249R9FKED: RES, 49.9, 1%, 0.063 W, 0402; Manufacturer: Vishay-Dale; CompType: Resistor; Value: 49.9; Value_Code: 49R9; Tolerance_%: 1; Power_W: 0.063; Value2: 0.063W; VDC_V: 50; TempCo: 100 ppm/C; EIA_Code: E96; U/M: EA; AEC Category: Q200
R16 = RNCF0603TKY4K99: RES, 4.99 k, 0.01%, 0.1 W, 0603; Manufacturer: Stackpole Electronics Inc; CompType: Resistor; Value: 4.99k; Res_ohm: 4990; Value_Code: 4k99; Tolerance_%: 0.01; Power_W: 0.1; Value2: 0.1W; VDC_V: 75; TempCo: 5 ppm/C; EIA_Code: E192; U/M: EA; AEC Category: Q200; AEC Qualified: N
R18 = RN73C2A82K5BTDF: RES, 82.5 k, 0.1%, 0.1 W, 0805; Manufacturer: TE Connectivity; CompType: Resistor; Value: 82.5k; Res_ohm: 82500; Value_Code: 82k5; Tolerance_%: 0.1; Value2: 0.1W; VDC_V: 100; TempCo: 10 ppm/C; EIA_Code: E192; U/M: EA; AEC Category: Q200; AEC Qualified: N
R19 = RN73C2A17K8BTDF: RES, 17.8 k, 0.1%, 0.1 W, 0805; Manufacturer: TE Connectivity; CompType: Resistor; Value: 17.8k; Res_ohm: 17800; Value_Code: 17k8; Tolerance_%: 0.1; Value2: 0.1W; VDC_V: 100; TempCo: 10 ppm/C; EIA_Code: E192; U/M: EA; AEC Category: Q200; AEC Qualified: N
R25 = RN73C2A27R4BTDF: RES, 27.4, 0.1%, 0.1 W, 0805; Manufacturer: TE Connectivity; CompType: Resistor; Value: 27.4; Value_Code: 27R4; Tolerance_%: 0.1; Value2: 0.1W; VDC_V: 100; TempCo: 10 ppm/C; EIA_Code: E192; U/M: EA; AEC Category: Q200; AEC Qualified: N
TP4-TP6 = TESTPOINT: TEST POINT.  No entry in BOM.

## Sheet TIDA_01438_TID_Power.SchDoc
size 431 x 279 mm; Date: Not shown in title block; ApprovedBy: Not shown in title block; CheckedBy: Not shown in title block; Author: Not shown in title block; CompanyName: Not shown in title block; Engineer: Not shown in title block; Organization: Not shown in title block; Address1: Not shown in title block; Address2: Not shown in title block; Address3: Not shown in title block; Address4: Not shown in title block; DocumentNumber: 1; Revision: Use project parameter SCH_Rev; SheetNumber: 2; SheetTotal: 3; PageSetup: Record=PageOptions¦CenterHorizontal=True¦CenterVertical=True¦PrintScale=0.62¦XCorrection=1.00¦YCorrection=1.00¦PrintKind=0¦BorderSize=5000000¦LeftOffset=0¦BottomOffset=0¦Orientation=2¦PaperLength=1000¦PaperWidth=1000¦Scale=100¦PaperSource=15¦PrintQuality=600¦MediaType=1¦DitherType=10¦PrintScaleMode=1¦PaperKind=Letter
Used 2 times, as channels CH1/PWR, CH2/PWR. Parts and nets are listed once, with the designators drawn on the sheet.
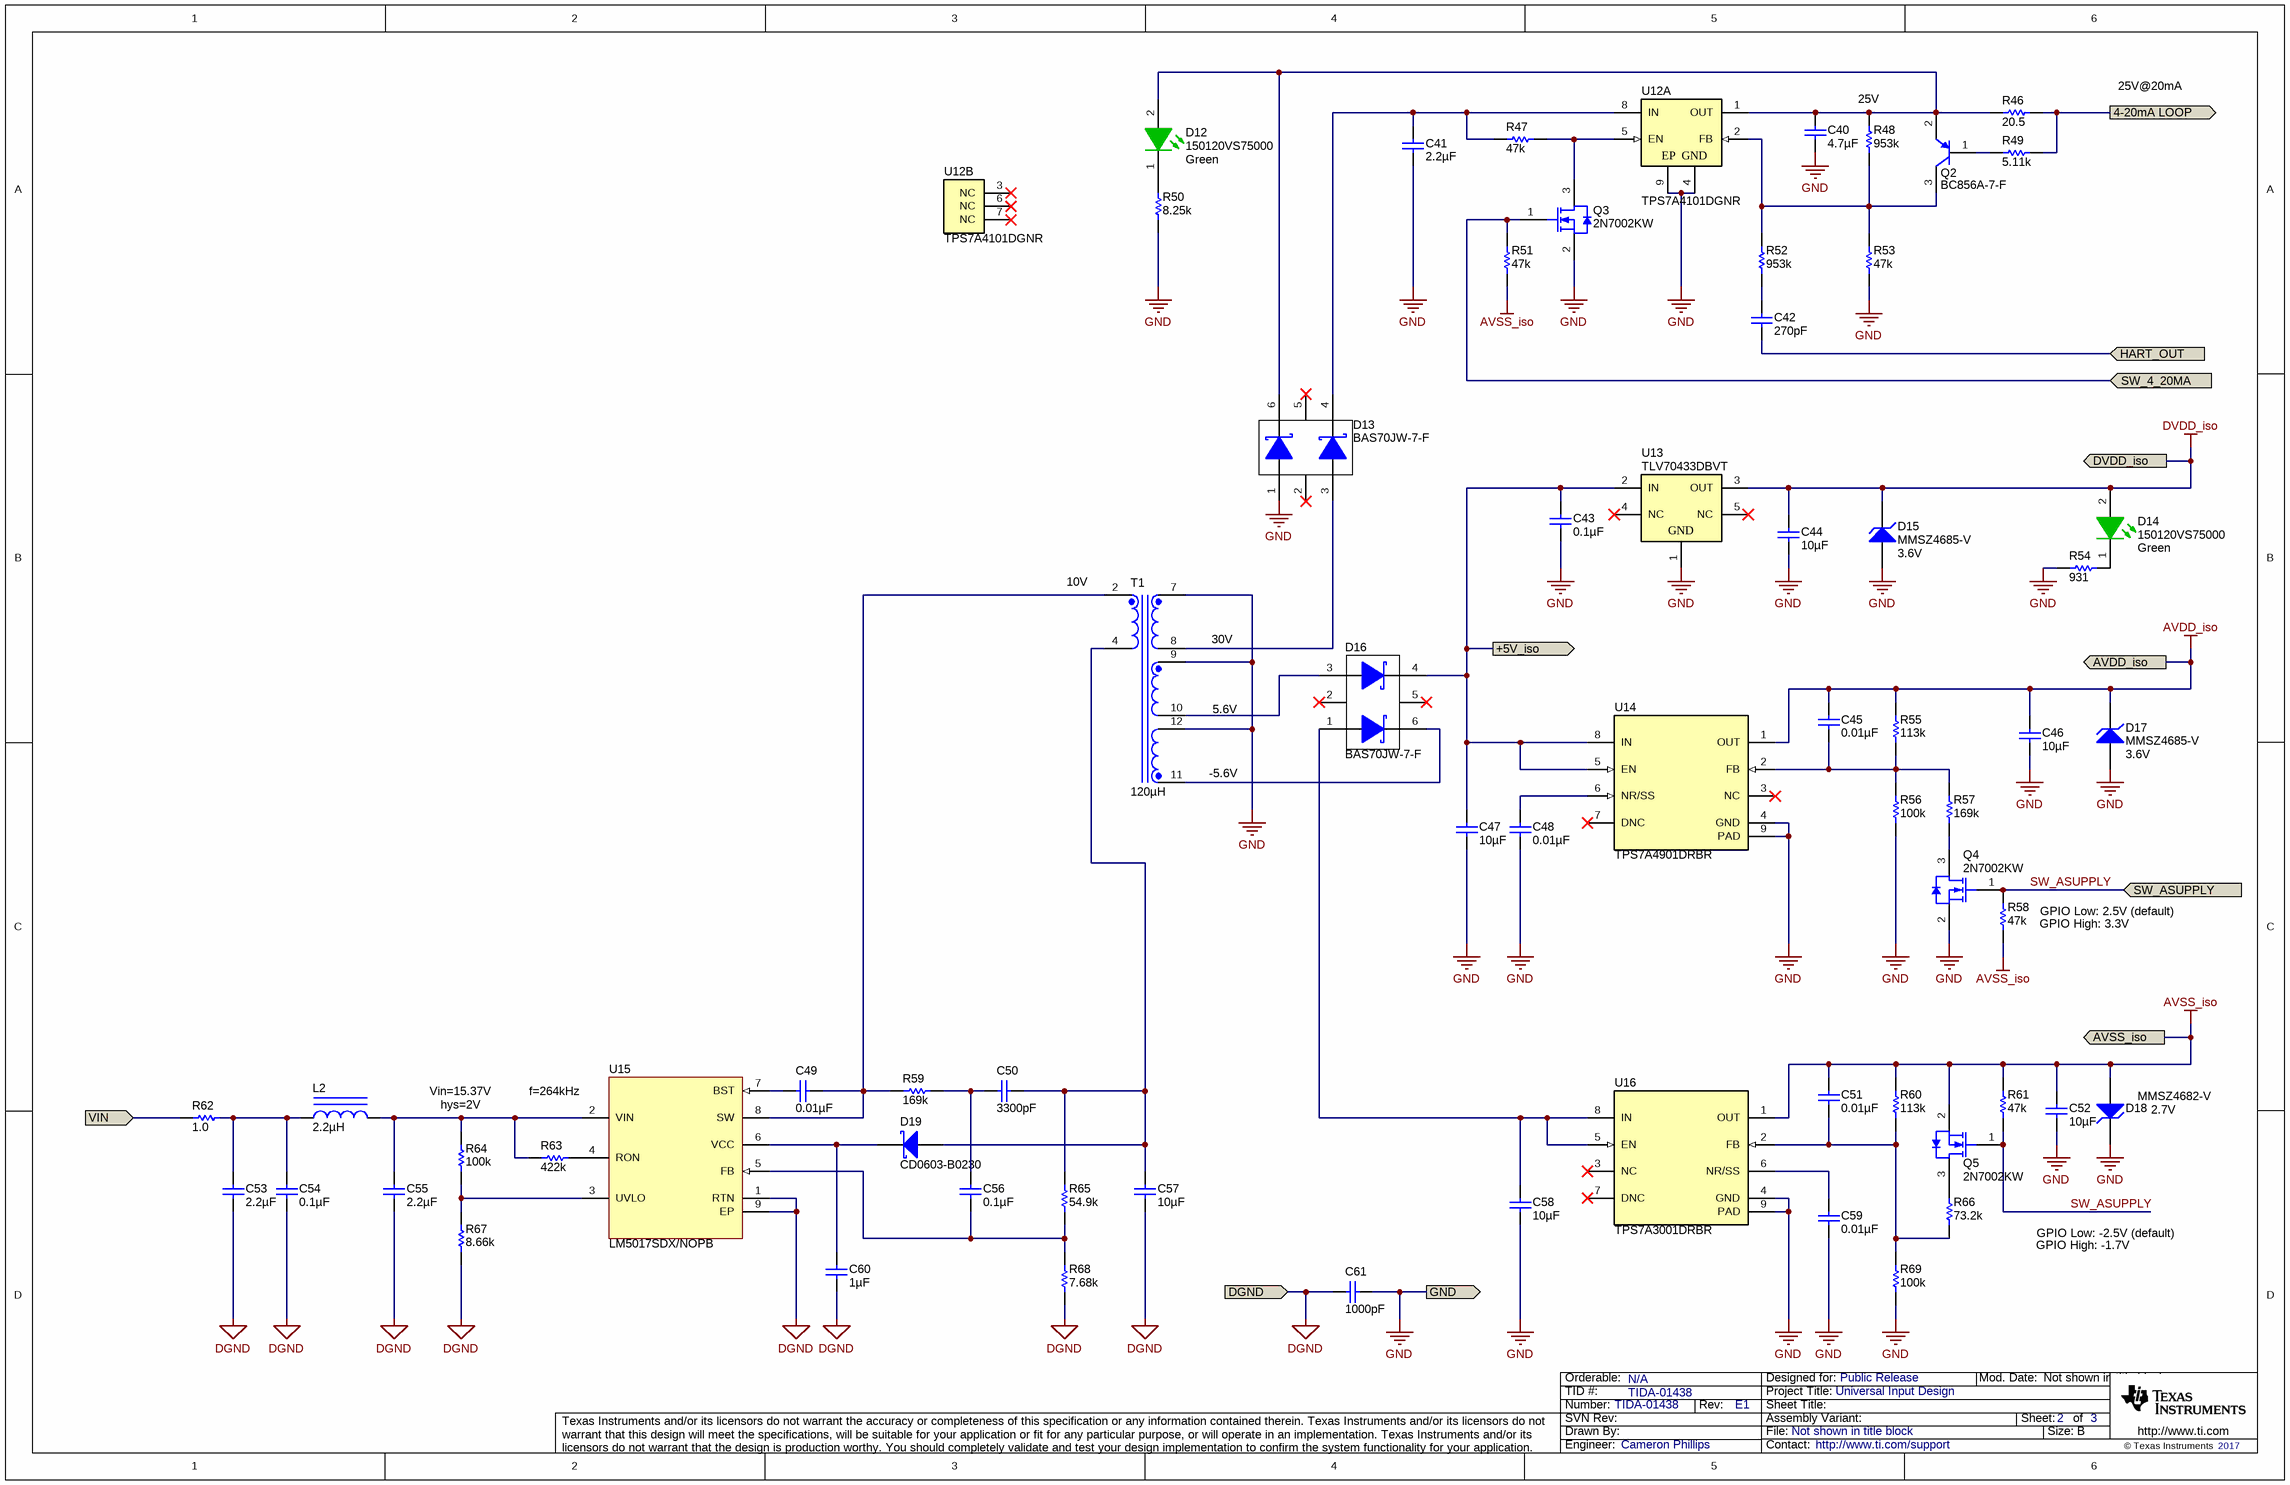
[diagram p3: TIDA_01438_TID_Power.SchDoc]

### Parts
C40  ValueDisplayed: 4.7µF  [1206_190]  (hidden comment: C3216X7R1H475M160AC)
C41  ValueDisplayed: 2.2µF  [1206]  (hidden comment: UMK316B7225KL-T)
C42  ValueDisplayed: 270pF  [0402]  (hidden comment: GRM155R71H271KA01D)
C43  ValueDisplayed: 0.1µF  [0402]  (hidden comment: C1005X7R1H104K)
C44  ValueDisplayed: 10µF  [1206]  (hidden comment: C3216X7R1C106M)
C45  ValueDisplayed: 0.01µF  [0402]  (hidden comment: GRM155R71E103KA01D)
C46  ValueDisplayed: 10µF  [1206]  (hidden comment: C3216X7R1C106M)
C47  ValueDisplayed: 10µF  [1206]  (hidden comment: C3216X7R1C106M)
C48  ValueDisplayed: 0.01µF  [0402]  (hidden comment: GRM155R71E103KA01D)
C49  ValueDisplayed: 0.01µF  [0402]  (hidden comment: GRM155R71E103KA01D)
C50  ValueDisplayed: 3300pF  [0402]  (hidden comment: GRM155R71H332KA01D)
C51  ValueDisplayed: 0.01µF  [0402]  (hidden comment: GRM155R71E103KA01D)
C52  ValueDisplayed: 10µF  [1206]  (hidden comment: C3216X7R1C106M)
C53  ValueDisplayed: 2.2µF  [1206]  (hidden comment: UMK316B7225KL-T)
C54  ValueDisplayed: 0.1µF  [0402]  (hidden comment: C1005X7R1H104K)
C55  ValueDisplayed: 2.2µF  [1206]  (hidden comment: UMK316B7225KL-T)
C56  ValueDisplayed: 0.1µF  [0402]  (hidden comment: C1005X7R1H104K)
C57  ValueDisplayed: 10µF  [1206]  (hidden comment: GRM31CR71E106KA12L)
C58  ValueDisplayed: 10µF  [1206]  (hidden comment: C3216X7R1C106M)
C59  ValueDisplayed: 0.01µF  [0402]  (hidden comment: GRM155R71E103KA01D)
C60  ValueDisplayed: 1µF  [0603]  (hidden comment: GRM188R71E105KA12D)
C61  ValueDisplayed: 1000pF  [1206_190]  (hidden comment: 202R18W102KV4E)
D12  150120VS75000  value Green  [WL_SMCW_GREEN_1206]
D13  BAS70JW-7-F  [SOT-363]
D14  150120VS75000  value Green  [WL_SMCW_GREEN_1206]
D15  MMSZ4685-V  value 3.6V  [SOD-123]
D16  BAS70JW-7-F  [SOT-363]
D17  MMSZ4685-V  value 3.6V  [SOD-123]
D18  MMSZ4682-V  value 2.7V  [SOD-123]
D19  CD0603-B0230  [Diode_0603]
L2  ValueDisplayed: 2.2µH  [0603]  (hidden comment: LQM18PN2R2MFH)
Q2  BC856A-7-F  [SOT-23]
Q3  2N7002KW  [SOT-323]
Q4  2N7002KW  [SOT-323]
Q5  2N7002KW  [SOT-323]
R46  ValueDisplayed: 20.5  [1206]  (hidden comment: CRCW120620R5FKEA)
R47  ValueDisplayed: 47k  [0402]  (hidden comment: CRCW040247K0JNED)
R48  ValueDisplayed: 953k  [0402]  (hidden comment: CRCW0402953KFKED)
R49  ValueDisplayed: 5.11k  [0402]  (hidden comment: CRCW04025K11FKED)
R50  ValueDisplayed: 8.25k  [0402]  (hidden comment: CRCW04028K25FKED)
R51  ValueDisplayed: 47k  [0402]  (hidden comment: CRCW040247K0JNED)
R52  ValueDisplayed: 953k  [0402]  (hidden comment: CRCW0402953KFKED)
R53  ValueDisplayed: 47k  [0402]  (hidden comment: CRCW040247K0JNED)
R54  ValueDisplayed: 931  [0402]  (hidden comment: CRCW0402931RFKED)
R55  ValueDisplayed: 113k  [0402]  (hidden comment: CRCW0402113KFKED)
R56  ValueDisplayed: 100k  [0402]  (hidden comment: CRCW0402100KFKED)
R57  ValueDisplayed: 169k  [0402]  (hidden comment: CRCW0402169KFKED)
R58  ValueDisplayed: 47k  [0402]  (hidden comment: CRCW040247K0JNED)
R59  ValueDisplayed: 169k  [0402]  (hidden comment: CRCW0402169KFKED)
R60  ValueDisplayed: 113k  [0402]  (hidden comment: CRCW0402113KFKED)
R61  ValueDisplayed: 47k  [0402]  (hidden comment: CRCW040247K0JNED)
R62  ValueDisplayed: 1.0  [0402]  (hidden comment: CRCW04021R00JNED)
R63  ValueDisplayed: 422k  [0402]  (hidden comment: CRCW0402422KFKED)
R64  ValueDisplayed: 100k  [0402]  (hidden comment: CRCW0402100KFKED)
R65  ValueDisplayed: 54.9k  [0402]  (hidden comment: CRCW040254K9FKED)
R66  ValueDisplayed: 73.2k  [0402]  (hidden comment: CRCW040273K2FKED)
R67  ValueDisplayed: 8.66k  [0402]  (hidden comment: CRCW04028K66FKED)
R68  ValueDisplayed: 7.68k  [0402]  (hidden comment: CRCW04027K68FKED)
R69  ValueDisplayed: 100k  [0402]  (hidden comment: CRCW0402100KFKED)
T1  ValueDisplayed: 120µH  [Wurth_750315856]  (hidden comment: 750315856)
U12  TPS7A4101DGNR  [DGN0008B_N]  (parts A,B of 2)
U13  TLV70433DBVT  [DBV0005A_N]
U14  TPS7A4901DRBR  [DRB0008A]
U15  LM5017SDX/NOPB  [NGU0008B]
U16  TPS7A3001DRBR  [DRB0008A]

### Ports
4-20mA LOOP (out), +5V_iso (out), AVDD_iso (out), AVSS_iso (out), DGND (in), DVDD_iso (out), GND (out), HART_OUT (in), SW_4_20MA (in), SW_ASUPPLY (in), VIN (in)

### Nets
AVDD_iso: C45.1 C46.1 D17.1(K) R55.2 U14.1(OUT) ; port AVDD_iso
AVSS_iso: C51.1 C52.1 D18.2(A) Q5.2(S) R51.1 R58.2 R60.2 R61.2 U16.1(OUT) ; port AVSS_iso
DGND: C53.2 C54.2 C55.2 C57.2 C60.2 C61.2 R67.1 R68.1 U15.1(RTN) U15.9(EP) ; port DGND
DVDD_iso: C44.1 D14.2(A) D15.1(K) U13.3(OUT) ; port DVDD_iso
GND: C40.2 C41.2 C43.2 C44.2 C46.2 C47.2 C48.2 C52.2 C58.2 C59.2 C61.1 D13.1(A) D15.2(A) D17.2(A) D18.1(K) Q3.2(S) Q4.2(S) R50.1 R53.1 R54.2 R56.1 R69.1 T1.7 T1.9 T1.12 U12.4(GND) U12.9(EP) U13.1(GND) U14.4(GND) U14.9(PAD) U16.4(GND) U16.9(PAD) ; port GND
4-20mA LOOP: R46.1 R49.2 ; port 4-20mA LOOP
+5V_iso: C43.1 C47.1 D16.4(C) U13.2(IN) U14.5(EN) U14.8(IN) ; port +5V_iso
HART_OUT: C42.2 ; port HART_OUT
SW_4_20MA: Q3.1(G) R51.2 ; port SW_4_20MA
SW_ASUPPLY: Q4.1(G) Q5.1(G) R58.1 R61.1 ; port SW_ASUPPLY
VIN: R62.1 ; port VIN
NetC40_1: C40.1 D12.2(A) D13.6(C) Q2.2(E) R46.2 R48.1 U12.1(OUT)
NetC41_1: C41.1 D13.4(C) R47.1 U12.8(IN)
NetC42_1: C42.1 R52.2
NetC45_2: C45.2 R55.1 R56.2 R57.1 U14.2(FB)
NetC48_1: C48.1 U14.6(NR/SS)
NetC49_1: C49.1 R59.2 T1.2 U15.8(SW)
NetC49_2: C49.2 U15.7(BST)
NetC50_1: C50.1 C57.1 D19.2(A) R65.2 T1.4
NetC50_2: C50.2 C56.1 R59.1
NetC51_2: C51.2 R60.1 R66.2 R69.2 U16.2(FB)
NetC53_1: C53.1 C54.1 L2.1 R62.2
NetC55_1: C55.1 L2.2 R63.2 R64.2 U15.2(VIN)
NetC56_2: C56.2 R65.1 R68.2 U15.5(FB)
NetC58_1: C58.1 D16.1(A) U16.5(EN) U16.8(IN)
NetC59_1: C59.1 U16.6(NR/SS)
NetC60_1: C60.1 D19.1(K) U15.6(VCC)
NetD12_1: D12.1(K) R50.2
NetD13_3: D13.3(A) T1.8
NetD14_1: D14.1(K) R54.1
NetD16_3: D16.3(A) T1.10
NetD16_6: D16.6(C) T1.11
NetQ2_1: Q2.1(B) R49.1
NetQ2_3: Q2.3(C) R48.2 R52.1 R53.2 U12.2(FB)
NetQ3_3: Q3.3(D) R47.2 U12.5(EN)
NetQ4_3: Q4.3(D) R57.2
NetQ5_3: Q5.3(D) R66.1
NetR63_1: R63.1 U15.4(RON)
NetR64_1: R64.1 R67.2 U15.3(UVLO)

Not connected (* = marked no-connect by the designer): D13 2(NC)* 5(NC)*; D16 2(NC)* 5(NC)*; U12 3(NC)* 6(NC)* 7(NC)*; U13 4(NC)* 5(NC)*; U14 3(NC)* 7(DNC)*; U16 3(NC)* 7(DNC)*

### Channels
CH1/PWR: designators end in _PWR1; ports 4-20mA LOOP=4-20mA LOOP +5V_iso=+5V_iso AVDD_iso=AVDD_iso AVSS_iso=AVSS_iso DGND=DGND DVDD_iso=DVDD_iso GND=GND HART_OUT=HART_OUT SW_4_20MA=SW_4_20MA SW_ASUPPLY=SW_ASUPPLY VIN=VIN
CH2/PWR: designators end in _PWR2; ports 4-20mA LOOP=4-20mA LOOP +5V_iso=+5V_iso AVDD_iso=AVDD_iso AVSS_iso=AVSS_iso DGND=DGND DVDD_iso=DVDD_iso GND=GND HART_OUT=HART_OUT SW_4_20MA=SW_4_20MA SW_ASUPPLY=SW_ASUPPLY VIN=VIN

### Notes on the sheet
- (near R48) 25V
- 25V@20mA
- (near T1) 10V
- 30V
- 5.6V
- (near T1) -5.6V
- (near R58) GPIO High: 3.3V
- (near R58) GPIO Low: 2.5V (default)
- Vin=15.37V
- (near R64) hys=2V
- (near U15) f=264kHz
- GPIO High: -1.7V
- GPIO Low: -2.5V (default)

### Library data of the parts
C40 = C3216X7R1H475M160AC: as C35 on sheet TIDA_01438_TID_Cape
C41 C53 C55 = UMK316B7225KL-T: as C39 on sheet TIDA_01438_TID_Cape
C42 = GRM155R71H271KA01D: CAP, CERM, 270 pF, 50 V, +/- 10%, X7R, 0402; Manufacturer: MuRata; Polarized: N; CompType: Capacitor; Value: 270pF; U/M: EA; Cap_F: 0.00000000027; Tolerance_%: 10; Value1: Unknown; VDC_V: 50; Value2: 50V; TaMin_C: -55; TaMax_C: 125
C43 C54 C56 = C1005X7R1H104K: as C31 on sheet TIDA_01438_TID_Cape
C44 C46 C47 C52 C58 = C3216X7R1C106M: CAP, CERM, 10 µF, 16 V, +/- 20%, X7R, 1206; Manufacturer: TDK; Polarized: N; CompType: Capacitor; Value: 10uF; U/M: EA; Cap_F: 0.00001; Tolerance_%: 20; ESR_ohm: 0.0046; Value1: 0.0046 ohm; VDC_V: 16; Value2: 16V; TaMin_C: -55; TaMax_C: 125; AEC Category: Q200
C45 C48 C49 C51 C59 = GRM155R71E103KA01D: CAP, CERM, 0.01 µF, 25 V, +/- 10%, X7R, 0402; Manufacturer: MuRata; Polarized: N; CompType: Capacitor; Value: 0.01uF; U/M: EA; Cap_F: 0.00000001; Tolerance_%: 10; Value1: Unknown; VDC_V: 25; Value2: 25V; TaMin_C: -55; TaMax_C: 125; AEC Category: Q200
C50 = GRM155R71H332KA01D: CAP, CERM, 3300 pF, 50 V, +/- 10%, X7R, 0402; Manufacturer: MuRata; Polarized: N; CompType: Capacitor; Value: 3300pF; U/M: EA; Cap_F: 0.0000000033; Tolerance_%: 10; Value1: Unknown; VDC_V: 50; Value2: 50V; TaMin_C: -55; TaMax_C: 125; AEC Category: Q200
C57 = GRM31CR71E106KA12L: CAP, CERM, 10 µF, 25 V, +/- 10%, X7R, 1206; Manufacturer: MuRata; Polarized: N; CompType: Capacitor; Value: 10uF; U/M: EA; Cap_F: 0.00001; Tolerance_%: 10; Value1: Unknown; VDC_V: 25; Value2: 25V; TaMin_C: -55; TaMax_C: 125; Cap_Case: 2220; AEC Category: Q200
C60 = GRM188R71E105KA12D: CAP, CERM, 1 µF, 25 V, +/- 10%, X7R, 0603; Manufacturer: MuRata; Polarized: N; CompType: Capacitor; Value: 1uF; U/M: EA; Cap_F: 0.000001; Tolerance_%: 10; Value1: Unknown; VDC_V: 25; Value2: 25V; TaMin_C: -55; TaMax_C: 125; AEC Category: Q200
C61 = 202R18W102KV4E: CAP, CERM, 1000 pF, 2000 V, +/- 10%, X7R, 1206_190; Manufacturer: Johanson Technology; Polarized: N; CompType: Capacitor; Value: 1000pF; U/M: EA; Cap_F: 0.000000001; Tolerance_%: 10; Value1: Unknown; VDC_V: 2000; Value2: 2000V; TaMin_C: -55; TaMax_C: 125; Cap_Case: 1206; AEC Category: Q200
D12 D14 = 150120VS75000: as D11 on sheet TIDA_01438_TID_Cape
D13 D16 = BAS70JW-7-F: as D4 on sheet TIDA_01438_TID_AFE
D15 D17 = MMSZ4685-V: Diode, Zener, 3.6 V, 500 mW, SOD-123; Manufacturer: Vishay-Semiconductor; SymbolCreator: a0412235; U/M: EA; Power_W: 0.5; Vz_V: 3.6; Value1: 0.5W; RJA_CperW: 67; AEC Category: Q101
D18 = MMSZ4682-V: Diode, Zener, 2.7 V, 500 mW, SOD-123; Manufacturer: Vishay-Semiconductor; SymbolCreator: a0412235; U/M: EA; Power_W: 0.5; Vz_V: 2.7; Value1: 0.5W; RJA_CperW: 67; AEC Category: Q101
D19 = CD0603-B0230: Diode, Schottky, 35 V, 0.2 A, 0603 Diode; Manufacturer: Bourns; U/M: EA; Vf_V: 0.5; Value: 35V; Value1: 0.2A; Value2: 0.5V; Io_A: 0.2; Vr_V: 35; TJmax_C: 125
L2 = LQM18PN2R2MFH: Inductor, Ferrite, 2.2 µH, 0.35 A, 0.38 ohm, SMD; Manufacturer: MuRata; Value: 2.2uH; Ind_H: 2.2E-6; Imax_A: 0.35; Irms: 0.9A @ 40C rise; Isat: 0.35A @ 30% inductance drop; DCR_ohm: 0.38; Value2: 0.35A; AEC Category: Q200
Q2 = BC856A-7-F, Diodes Inc.: Transistor, PNP, 65 V, 0.01 A, SOT-23; CompType: BJT; PNP: 1; NPN: 0; Vceo_V: 65; Vcesat1_V: 0.3; Value: 65 V; IcRated_A: 0.01; Value1: 0.01 A; TaMin_C: -65; TaMax_C: 150; U/M: EA; AEC Category: Q101
Q3-Q5 = 2N7002KW: as Q1 on sheet TIDA_01438_TID_Cape
R46 = CRCW120620R5FKEA: RES, 20.5, 1%, 0.25 W, 1206; Manufacturer: Vishay-Dale; CompType: Resistor; Value: 20.5; Value_Code: 20R5; Tolerance_%: 1; Power_W: 0.25; Value2: 0.25W; VDC_V: 200; TempCo: 100 ppm/C; EIA_Code: E96; U/M: EA; AEC Category: Q200
R47 R51 R53 R58 R61 = CRCW040247K0JNED: as R34 on sheet TIDA_01438_TID_Cape
R48 R52 = CRCW0402953KFKED: RES, 953 k, 1%, 0.063 W, 0402; Manufacturer: Vishay-Dale; CompType: Resistor; Value: 953k; Res_ohm: 953000; Tolerance_%: 1; Power_W: 0.063; Value2: 0.063W; VDC_V: 50; TempCo: 100 ppm/C; EIA_Code: E96; U/M: EA; AEC Category: Q200
R49 = CRCW04025K11FKED: RES, 5.11 k, 1%, 0.063 W, 0402; Manufacturer: Vishay-Dale; CompType: Resistor; Value: 5.11k; Res_ohm: 5110; Value_Code: 5k11; Tolerance_%: 1; Power_W: 0.063; Value2: 0.063W; VDC_V: 50; TempCo: 100 ppm/C; EIA_Code: E96; U/M: EA
R50 = CRCW04028K25FKED: as R45 on sheet TIDA_01438_TID_Cape
R54 = CRCW0402931RFKED: RES, 931, 1%, 0.063 W, 0402; Manufacturer: Vishay-Dale; CompType: Resistor; Value: 931; Value_Code: 931R; Tolerance_%: 1; Power_W: 0.063; Value2: 0.063W; VDC_V: 50; TempCo: 100 ppm/C; EIA_Code: E96; U/M: EA; AEC Category: Q200
R55 R60 = CRCW0402113KFKED: RES, 113 k, 1%, 0.063 W, 0402; Manufacturer: Vishay-Dale; CompType: Resistor; Value: 113k; Res_ohm: 113000; Tolerance_%: 1; Power_W: 0.063; Value2: 0.063W; VDC_V: 50; TempCo: 100 ppm/C; EIA_Code: E96; U/M: EA; AEC Category: Q200
R56 R64 R69 = CRCW0402100KFKED: as R40 on sheet TIDA_01438_TID_Cape
R57 R59 = CRCW0402169KFKED: RES, 169 k, 1%, 0.063 W, 0402; Manufacturer: Vishay-Dale; CompType: Resistor; Value: 169k; Res_ohm: 169000; Tolerance_%: 1; Power_W: 0.063; Value2: 0.063W; VDC_V: 50; TempCo: 100 ppm/C; EIA_Code: E96; U/M: EA; AEC Category: Q200
R62 = CRCW04021R00JNED: RES, 1.0, 5%, 0.063 W, 0402; Manufacturer: Vishay-Dale; CompType: Resistor; Value: 1.0; Res_ohm: 1; Value_Code: 1R00; Tolerance_%: 5; Power_W: 0.063; Value2: 0.063W; VDC_V: 50; TempCo: 200 ppm/C; EIA_Code: E24; U/M: EA; AEC Category: Q200
R63 = CRCW0402422KFKED: RES, 422 k, 1%, 0.063 W, 0402; Manufacturer: Vishay-Dale; CompType: Resistor; Value: 422k; Res_ohm: 422000; Tolerance_%: 1; Power_W: 0.063; Value2: 0.063W; VDC_V: 50; TempCo: 100 ppm/C; EIA_Code: E96; U/M: EA; AEC Category: Q200
R65 = CRCW040254K9FKED: RES, 54.9 k, 1%, 0.063 W, 0402; Manufacturer: Vishay-Dale; CompType: Resistor; Value: 54.9k; Res_ohm: 54900; Value_Code: 54k9; Tolerance_%: 1; Power_W: 0.063; Value2: 0.063W; VDC_V: 50; TempCo: 100 ppm/C; EIA_Code: E96; U/M: EA; AEC Category: Q200
R66 = CRCW040273K2FKED: RES, 73.2 k, 1%, 0.063 W, 0402; Manufacturer: Vishay-Dale; CompType: Resistor; Value: 73.2k; Res_ohm: 73200; Value_Code: 73k2; Tolerance_%: 1; Power_W: 0.063; Value2: 0.063W; VDC_V: 50; TempCo: 100 ppm/C; EIA_Code: E96; U/M: EA; AEC Category: Q200
R67 = CRCW04028K66FKED: RES, 8.66 k, 1%, 0.063 W, 0402; Manufacturer: Vishay-Dale; CompType: Resistor; Value: 8.66k; Res_ohm: 8660; Value_Code: 8k66; Tolerance_%: 1; Power_W: 0.063; Value2: 0.063W; VDC_V: 50; TempCo: 100 ppm/C; EIA_Code: E96; U/M: EA; AEC Category: Q200
R68 = CRCW04027K68FKED: RES, 7.68 k, 1%, 0.063 W, 0402; Manufacturer: Vishay-Dale; CompType: Resistor; Value: 7.68k; Res_ohm: 7680; Value_Code: 7k68; Tolerance_%: 1; Power_W: 0.063; Value2: 0.063W; VDC_V: 50; TempCo: 100 ppm/C; EIA_Code: E96; U/M: EA; AEC Category: Q200
T1 = 750315856: Transformer, 120 uH, SMT; Manufacturer: Wurth Elektronik; SymbolCreator: Altium; Value: 120uH; Lp: 120; DCR_ohm: 0.24
U12 = TPS7A4101DGNR: Single Output LDO, 50 mA, Adjustable 1.175 to 48 V Output, 7 to 50 V Input, 8-pin MSOP (DGN), -40 to 125 degC, Green (RoHS & no Sb/Br); Manufacturer: Texas Instruments; Alternate PartNumber: Equivalent; Accuracy(%): 1; Iout(Max)(A): 0.05; Iq(Typ)(mA): 0.02; SubFamily: Single Channel LDO; Vdo(Typ)(mV): 290; Vin(Max)(V): 50; Vin(Min)(V): 7; Vout Adj(Max)(V): 48; Vout Adj(Min)(V): 1.161
U13 = TLV70433DBVT: Single Output LDO, 150 mA, Fixed 3.3 V Output, 2.5 to 24 V Input, with Ultra-Low IQ, 5-pin SOT-23 (DBV), -40 to 125 degC, Green (RoHS & no Sb/Br); Manufacturer: Texas Instruments; Alternate PartNumber: Equivalent; Accuracy(%): 2; Fixed Output Options(V): 3.3; Iout(Max)(A): 0.15; Iq(Typ)(mA): 0.003; SubFamily: Single Channel LDO; Vdo(Typ)(mV): 400; Vin(Max)(V): 24; Vin(Min)(V): 2.5
U14 = TPS7A4901DRBR: +36V, +150mA, Ultralow-Noise, Positive LINEAR REGULATOR, DRB0008A; Alternate PartNumber: TPS7A4901DRBT; Manufacturer: Texas Instruments; SymbolCreator: a0411947; CompType: IC; U/M: EA
U15 = LM5017SDX/NOPB: 100V, 600mA Constant On-Time Synchronous Buck Regulator, NGU0008B; Alternate PartNumber: LM5017SD/NOPB; Manufacturer: Texas Instruments; SymbolCreator: a0412235; CompType: IC; U/M: EA
U16 = TPS7A3001DRBR: -35-V, -200-mA, Ultralow-Noise, Negative Linear Regulator, DRB0008A; Alternate PartNumber: TPS7A3001DRBT; Manufacturer: Texas Instruments; SymbolCreator: Altium; CompType: IC; U/M: EA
